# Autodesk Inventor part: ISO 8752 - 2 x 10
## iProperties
Author: Ulrich
Created: 2004-10
Part Number: ISO 8752 - 2 x 10
Material: Standard
Catalog Web Link: file:///C:/Programme/Autodesk/Inventor 5.3/Content/Din/index.htm?doNavigateId=75DC2E92-CB48-11D4-A9FB-0080AD303E0A|0557C0AEB16611D4BA6900C04F798F98|true
Description: Spannstift
Document SubType Name: Standard Catalog Part
Standard: ISO 8752 - 2 x 10
Designer: Ulrich
KLASSIFIKATION: 31163201 un/spsc
HERSTELLER: DIN Normsystem
Control State: 0
Master: False
Checked Out: False
PropertySet Name: Design Tracking Control
Shininess: 20.0
Angle Display Precision: 2
Document Length Units: 11269
Document Angle Units: 11283
Document Time Units: 11279
Document Mass Units: 11290
Document Length Units Precision: 3
Document Angle Units Precision: 2
Compacted: True
PropertySet Name: _Private Model Information
Density: 0.0
Volumn: 0.0
Area: 0.0
PropertySet Name: Model Information
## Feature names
1. Basis1
